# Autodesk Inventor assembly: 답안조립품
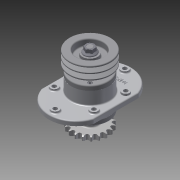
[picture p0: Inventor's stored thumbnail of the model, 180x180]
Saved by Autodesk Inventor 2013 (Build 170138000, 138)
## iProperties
Created: 2015-02
Part Number: 답안조립품
Document SubType Name: Assembly
Designer: kb
Author: kb
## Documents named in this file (11)
- C:\Users\kb\Desktop\450207V1001\답안조립품.iam
- C:\Users\kb\Desktop\450207V1001\본체.ipt
- C:\Users\kb\Desktop\450207V1001\2-커버.ipt
- C:\Users\kb\Desktop\450207V1001\3-축.ipt
- C:\Users\kb\Desktop\450207V1001\6-베어링 6206.ipt
- C:\Users\kb\Desktop\450207V1001\4-V벨트풀리.ipt
- C:\Users\kb\Desktop\450207V1001\11-키 6x6.ipt
- C:\Users\kb\Desktop\450207V1001\9-M16-너트.ipt
- C:\Users\kb\Desktop\450207V1001\5-체인 스프로킷.ipt
- C:\Users\kb\Desktop\450207V1001\7-부시.ipt
- C:\Users\kb\Desktop\450207V1001\10-M6.ipt
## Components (20 placed, 9 different names)
1. 2-커버:1
2. 2-커버:2
3. 3-축:1
4. 6-베어링 6206:1
5. 6-베어링 6206:2
6. 4-V벨트풀리:1
7. 11-키 6x6:1
8. 9-M16 너트:1
9. 5-체인 스프로킷:1
10. 11-키 6x6:2
11. 9-M16 너트:2
12. 7-부시:1
13. 10-M6:1
14. 10-M6:2
15. 10-M6:3
16. 10-M6:4
17. 10-M6:5
18. 10-M6:6
19. 10-M6:7
20. 10-M6:8
